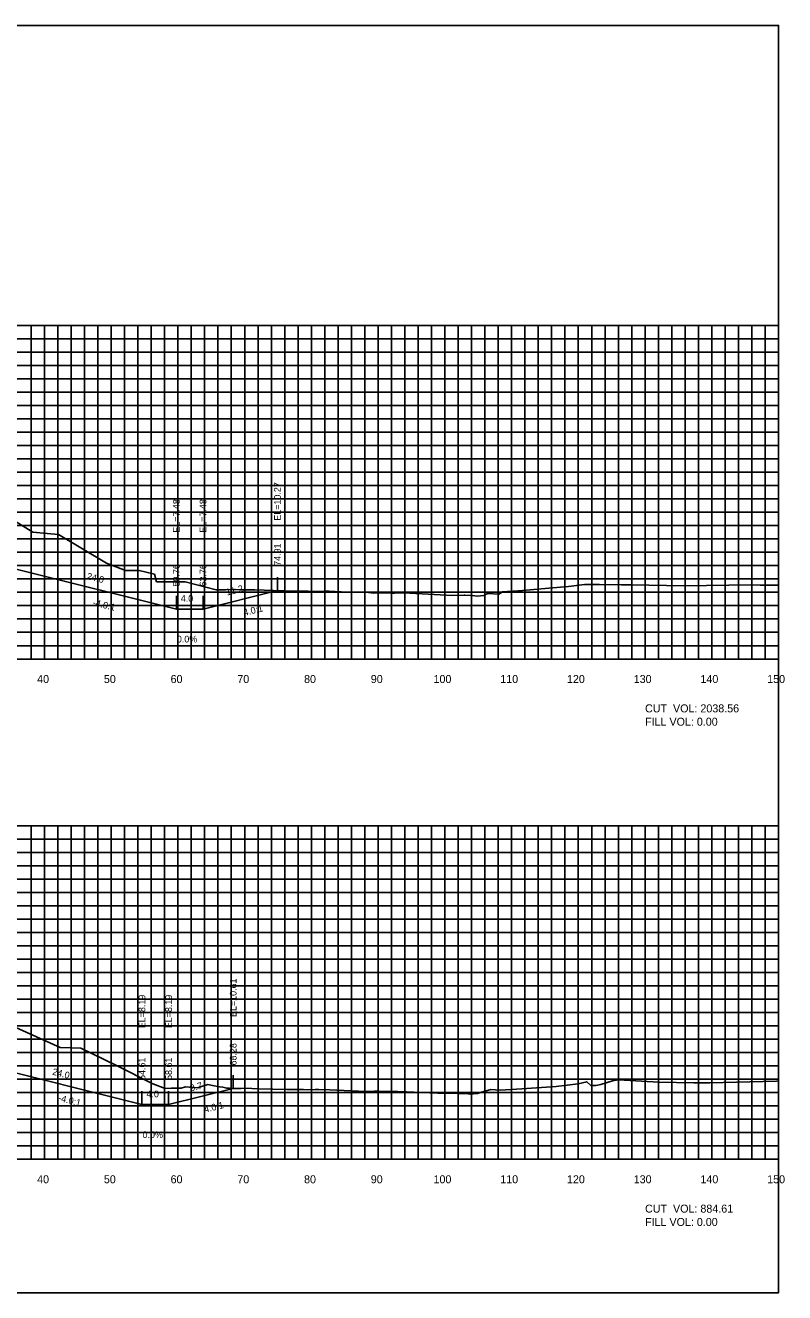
# Model space of a CAD drawing. Extents: x 1800976 to 1805104, y 250057 to 250580.
# Drawn here: x 1804368.1 to 1804481.9, y 250079.4 to 250269.4 of the extents above; entities that cross this region are included whole.
import ezdxf

# ---------------------------------------------------------------- set-up
doc = ezdxf.new("R2010")
doc.units = 0
for name, color, linetype in [('10', 7, 'Continuous'), ('3', 7, 'Continuous'), ('4', 7, 'Continuous'), ('60', 7, 'Continuous'), ('ANNO-TXT', 7, 'Continuous'), ('CL-CNST', 7, 'Continuous'), ('Level 62', 7, 'Continuous'), ('M-ROADS', 7, 'Continuous')]:
    doc.layers.add(name, color=color, linetype=linetype)

msp = doc.modelspace()

# ---------------------------------------------------------------- linework, layer by layer
for p, q in [((1804405.91, 250184.7), (1804405.91, 250186.7)), ((1804390.76, 250181.91), (1804390.76, 250183.91)), ((1804394.76, 250181.91), (1804394.76, 250183.91)), ((1804399.28, 250110.04), (1804399.28, 250112.04)), ((1804385.61, 250107.62), (1804385.61, 250109.62)), ((1804389.61, 250107.62), (1804389.61, 250109.62))]:
    msp.add_line(p, q)
msp.add_lwpolyline([(1804181, 250079.43), (1804481, 250079.43), (1804481, 250269.43), (1804181, 250269.43)], close=True)
at = {"layer": '60'}
for p, q in [((1804481, 250174.43), (1804481, 250224.43)), ((1804481.06, 250224.43), (1804481, 250224.43)), ((1804481.06, 250214.43), (1804481, 250214.43)), ((1804481.06, 250204.43), (1804481, 250204.43)), ((1804481.06, 250194.43), (1804481, 250194.43)), ((1804481.06, 250184.43), (1804481, 250184.43)), ((1804181, 250174.43), (1804481, 250174.43)), ((1804371, 250174.37), (1804371, 250174.43)), ((1804381, 250174.37), (1804381, 250174.43)), ((1804391, 250174.37), (1804391, 250174.43)), ((1804401, 250174.37), (1804401, 250174.43)), ((1804411, 250174.37), (1804411, 250174.43)), ((1804421, 250174.37), (1804421, 250174.43)), ((1804431, 250174.37), (1804431, 250174.43)), ((1804441, 250174.37), (1804441, 250174.43)), ((1804451, 250174.37), (1804451, 250174.43)), ((1804461, 250174.37), (1804461, 250174.43)), ((1804471, 250174.37), (1804471, 250174.43)), ((1804481, 250174.37), (1804481, 250174.43)), ((1804481.06, 250174.43), (1804481, 250174.43)), ((1804481, 250099.43), (1804481, 250149.43)), ((1804481.06, 250149.43), (1804481, 250149.43)), ((1804481.06, 250139.43), (1804481, 250139.43)), ((1804481.06, 250129.43), (1804481, 250129.43)), ((1804481.06, 250119.43), (1804481, 250119.43)), ((1804481.06, 250109.43), (1804481, 250109.43)), ((1804181, 250099.43), (1804481, 250099.43)), ((1804371, 250099.37), (1804371, 250099.43)), ((1804381, 250099.37), (1804381, 250099.43)), ((1804391, 250099.37), (1804391, 250099.43)), ((1804401, 250099.37), (1804401, 250099.43)), ((1804411, 250099.37), (1804411, 250099.43)), ((1804421, 250099.37), (1804421, 250099.43)), ((1804431, 250099.37), (1804431, 250099.43)), ((1804441, 250099.37), (1804441, 250099.43)), ((1804451, 250099.37), (1804451, 250099.43)), ((1804461, 250099.37), (1804461, 250099.43)), ((1804471, 250099.37), (1804471, 250099.43)), ((1804481, 250099.37), (1804481, 250099.43)), ((1804481.06, 250099.43), (1804481, 250099.43))]:
    msp.add_line(p, q, dxfattribs=at)
at = {"layer": 'CL-CNST'}
for points in [[(1804198.7, 250206.13), (1804259.65, 250185.81), (1804263.65, 250185.81), (1804284.65, 250189.31), (1804290.23, 250189.54), (1804294.23, 250189.7), (1804326.41, 250188.99), (1804326.81, 250188.98), (1804331, 250188.89), (1804356.21, 250188.33), (1804364.21, 250188.01), (1804366.76, 250187.91), (1804390.76, 250181.91), (1804394.76, 250181.91), (1804405.91, 250184.7)], [(1804287.75, 250115.49), (1804295, 250115.33), (1804331, 250114.54), (1804348.03, 250114.16), (1804356.03, 250113.84), (1804361.61, 250113.62), (1804385.61, 250107.62), (1804389.61, 250107.62), (1804399.28, 250110.04)]]:
    msp.add_lwpolyline(points, dxfattribs=at)
at = {"layer": 'Level 62'}
for p, q in [((1804181, 250224.43), (1804481, 250224.43)), ((1804369, 250174.43), (1804369, 250224.43)), ((1804371, 250174.43), (1804371, 250224.43)), ((1804373, 250174.43), (1804373, 250224.43)), ((1804375, 250174.43), (1804375, 250224.43)), ((1804377, 250174.43), (1804377, 250224.43)), ((1804379, 250174.43), (1804379, 250224.43)), ((1804381, 250174.43), (1804381, 250224.43)), ((1804383, 250174.43), (1804383, 250224.43)), ((1804385, 250174.43), (1804385, 250224.43)), ((1804387, 250174.43), (1804387, 250224.43)), ((1804389, 250174.43), (1804389, 250224.43)), ((1804391, 250174.43), (1804391, 250224.43)), ((1804393, 250174.43), (1804393, 250224.43)), ((1804395, 250174.43), (1804395, 250224.43)), ((1804397, 250174.43), (1804397, 250224.43)), ((1804399, 250174.43), (1804399, 250224.43)), ((1804401, 250174.43), (1804401, 250224.43)), ((1804403, 250174.43), (1804403, 250224.43)), ((1804405, 250174.43), (1804405, 250224.43)), ((1804407, 250174.43), (1804407, 250224.43)), ((1804409, 250174.43), (1804409, 250224.43)), ((1804411, 250174.43), (1804411, 250224.43)), ((1804413, 250174.43), (1804413, 250224.43)), ((1804415, 250174.43), (1804415, 250224.43)), ((1804417, 250174.43), (1804417, 250224.43)), ((1804419, 250174.43), (1804419, 250224.43)), ((1804421, 250174.43), (1804421, 250224.43)), ((1804423, 250174.43), (1804423, 250224.43)), ((1804425, 250174.43), (1804425, 250224.43)), ((1804427, 250174.43), (1804427, 250224.43)), ((1804429, 250174.43), (1804429, 250224.43)), ((1804431, 250174.43), (1804431, 250224.43)), ((1804433, 250174.43), (1804433, 250224.43)), ((1804435, 250174.43), (1804435, 250224.43)), ((1804437, 250174.43), (1804437, 250224.43)), ((1804439, 250174.43), (1804439, 250224.43)), ((1804441, 250174.43), (1804441, 250224.43)), ((1804443, 250174.43), (1804443, 250224.43)), ((1804445, 250174.43), (1804445, 250224.43)), ((1804447, 250174.43), (1804447, 250224.43)), ((1804449, 250174.43), (1804449, 250224.43)), ((1804451, 250174.43), (1804451, 250224.43)), ((1804453, 250174.43), (1804453, 250224.43)), ((1804455, 250174.43), (1804455, 250224.43)), ((1804457, 250174.43), (1804457, 250224.43)), ((1804459, 250174.43), (1804459, 250224.43)), ((1804461, 250174.43), (1804461, 250224.43)), ((1804463, 250174.43), (1804463, 250224.43)), ((1804465, 250174.43), (1804465, 250224.43)), ((1804467, 250174.43), (1804467, 250224.43)), ((1804469, 250174.43), (1804469, 250224.43)), ((1804471, 250174.43), (1804471, 250224.43)), ((1804473, 250174.43), (1804473, 250224.43)), ((1804475, 250174.43), (1804475, 250224.43)), ((1804477, 250174.43), (1804477, 250224.43)), ((1804479, 250174.43), (1804479, 250224.43)), ((1804481, 250174.43), (1804481, 250224.43)), ((1804181, 250222.43), (1804481, 250222.43)), ((1804181, 250220.43), (1804481, 250220.43)), ((1804181, 250218.43), (1804481, 250218.43)), ((1804181, 250216.43), (1804481, 250216.43)), ((1804181, 250214.43), (1804481, 250214.43)), ((1804181, 250212.43), (1804481, 250212.43)), ((1804181, 250210.43), (1804481, 250210.43)), ((1804181, 250208.43), (1804481, 250208.43)), ((1804181, 250206.43), (1804481, 250206.43)), ((1804181, 250204.43), (1804481, 250204.43)), ((1804181, 250202.43), (1804481, 250202.43)), ((1804181, 250200.43), (1804481, 250200.43)), ((1804181, 250198.43), (1804481, 250198.43)), ((1804181, 250196.43), (1804481, 250196.43)), ((1804181, 250194.43), (1804481, 250194.43)), ((1804181, 250192.43), (1804481, 250192.43)), ((1804181, 250190.43), (1804481, 250190.43)), ((1804181, 250188.43), (1804481, 250188.43)), ((1804181, 250186.43), (1804481, 250186.43)), ((1804181, 250184.43), (1804481, 250184.43)), ((1804181, 250182.43), (1804481, 250182.43)), ((1804181, 250180.43), (1804481, 250180.43)), ((1804181, 250178.43), (1804481, 250178.43)), ((1804181, 250176.43), (1804481, 250176.43)), ((1804181, 250174.43), (1804481, 250174.43)), ((1804181, 250149.43), (1804481, 250149.43)), ((1804369, 250099.43), (1804369, 250149.43)), ((1804371, 250099.43), (1804371, 250149.43)), ((1804373, 250099.43), (1804373, 250149.43)), ((1804375, 250099.43), (1804375, 250149.43)), ((1804377, 250099.43), (1804377, 250149.43)), ((1804379, 250099.43), (1804379, 250149.43)), ((1804381, 250099.43), (1804381, 250149.43)), ((1804383, 250099.43), (1804383, 250149.43)), ((1804385, 250099.43), (1804385, 250149.43)), ((1804387, 250099.43), (1804387, 250149.43)), ((1804389, 250099.43), (1804389, 250149.43)), ((1804391, 250099.43), (1804391, 250149.43)), ((1804393, 250099.43), (1804393, 250149.43)), ((1804395, 250099.43), (1804395, 250149.43)), ((1804397, 250099.43), (1804397, 250149.43)), ((1804399, 250099.43), (1804399, 250149.43)), ((1804401, 250099.43), (1804401, 250149.43)), ((1804403, 250099.43), (1804403, 250149.43)), ((1804405, 250099.43), (1804405, 250149.43)), ((1804407, 250099.43), (1804407, 250149.43)), ((1804409, 250099.43), (1804409, 250149.43)), ((1804411, 250099.43), (1804411, 250149.43)), ((1804413, 250099.43), (1804413, 250149.43)), ((1804415, 250099.43), (1804415, 250149.43)), ((1804417, 250099.43), (1804417, 250149.43)), ((1804419, 250099.43), (1804419, 250149.43)), ((1804421, 250099.43), (1804421, 250149.43)), ((1804423, 250099.43), (1804423, 250149.43)), ((1804425, 250099.43), (1804425, 250149.43)), ((1804427, 250099.43), (1804427, 250149.43)), ((1804429, 250099.43), (1804429, 250149.43)), ((1804431, 250099.43), (1804431, 250149.43)), ((1804433, 250099.43), (1804433, 250149.43)), ((1804435, 250099.43), (1804435, 250149.43)), ((1804437, 250099.43), (1804437, 250149.43)), ((1804439, 250099.43), (1804439, 250149.43)), ((1804441, 250099.43), (1804441, 250149.43)), ((1804443, 250099.43), (1804443, 250149.43)), ((1804445, 250099.43), (1804445, 250149.43)), ((1804447, 250099.43), (1804447, 250149.43)), ((1804449, 250099.43), (1804449, 250149.43)), ((1804451, 250099.43), (1804451, 250149.43)), ((1804453, 250099.43), (1804453, 250149.43)), ((1804455, 250099.43), (1804455, 250149.43)), ((1804457, 250099.43), (1804457, 250149.43)), ((1804459, 250099.43), (1804459, 250149.43)), ((1804461, 250099.43), (1804461, 250149.43)), ((1804463, 250099.43), (1804463, 250149.43)), ((1804465, 250099.43), (1804465, 250149.43)), ((1804467, 250099.43), (1804467, 250149.43)), ((1804469, 250099.43), (1804469, 250149.43)), ((1804471, 250099.43), (1804471, 250149.43)), ((1804473, 250099.43), (1804473, 250149.43)), ((1804475, 250099.43), (1804475, 250149.43)), ((1804477, 250099.43), (1804477, 250149.43)), ((1804479, 250099.43), (1804479, 250149.43)), ((1804481, 250099.43), (1804481, 250149.43)), ((1804181, 250147.43), (1804481, 250147.43)), ((1804181, 250145.43), (1804481, 250145.43)), ((1804181, 250143.43), (1804481, 250143.43)), ((1804181, 250141.43), (1804481, 250141.43)), ((1804181, 250139.43), (1804481, 250139.43)), ((1804181, 250137.43), (1804481, 250137.43)), ((1804181, 250135.43), (1804481, 250135.43)), ((1804181, 250133.43), (1804481, 250133.43)), ((1804181, 250131.43), (1804481, 250131.43)), ((1804181, 250129.43), (1804481, 250129.43)), ((1804181, 250127.43), (1804481, 250127.43)), ((1804181, 250125.43), (1804481, 250125.43)), ((1804181, 250123.43), (1804481, 250123.43)), ((1804181, 250121.43), (1804481, 250121.43)), ((1804181, 250119.43), (1804481, 250119.43)), ((1804181, 250117.43), (1804481, 250117.43)), ((1804181, 250115.43), (1804481, 250115.43)), ((1804181, 250113.43), (1804481, 250113.43)), ((1804181, 250111.43), (1804481, 250111.43)), ((1804181, 250109.43), (1804481, 250109.43)), ((1804181, 250107.43), (1804481, 250107.43)), ((1804181, 250105.43), (1804481, 250105.43)), ((1804181, 250103.43), (1804481, 250103.43)), ((1804181, 250101.43), (1804481, 250101.43)), ((1804181, 250099.43), (1804481, 250099.43))]:
    msp.add_line(p, q, dxfattribs=at)
at = {"layer": 'M-ROADS'}
for points in [[(1804359.51, 250199.42), (1804369.28, 250193.46), (1804371.41, 250193.26), (1804373.1, 250193.1), (1804380.3, 250188.78), (1804383.14, 250187.72), (1804383.93, 250187.72), (1804385.17, 250187.72), (1804387.48, 250187.15), (1804387.8, 250186.02), (1804389.44, 250186.02), (1804391.86, 250186.02), (1804391.98, 250186.02), (1804392.07, 250186), (1804396.74, 250184.8), (1804397.63, 250184.79), (1804397.7, 250184.79), (1804397.73, 250184.79), (1804398.13, 250184.81), (1804399.46, 250184.86), (1804399.61, 250184.85), (1804400.44, 250184.8), (1804400.6, 250184.79), (1804400.78, 250184.79), (1804401.05, 250184.79), (1804402.53, 250184.82), (1804405.34, 250184.72), (1804408.58, 250184.59), (1804410.16, 250184.61), (1804410.34, 250184.61), (1804410.37, 250184.61), (1804410.5, 250184.6), (1804411.4, 250184.57), (1804411.65, 250184.56), (1804412.92, 250184.58), (1804413.41, 250184.59), (1804413.68, 250184.58), (1804416.35, 250184.47), (1804418.24, 250184.47), (1804419.57, 250184.41), (1804420.36, 250184.32), (1804421.95, 250184.36), (1804422.13, 250184.36), (1804422.16, 250184.36), (1804422.25, 250184.35), (1804423.06, 250184.31), (1804423.43, 250184.29), (1804425.08, 250184.33), (1804425.19, 250184.33), (1804425.74, 250184.3), (1804432.12, 250183.97), (1804433.87, 250184), (1804433.93, 250184), (1804433.98, 250184), (1804434.86, 250183.97), (1804435.15, 250183.95), (1804435.86, 250183.83), (1804436.85, 250183.97), (1804437, 250184.06), (1804437.43, 250184.26), (1804439.07, 250184.17), (1804439.62, 250184.48), (1804441.91, 250184.64), (1804442.01, 250184.64), (1804442.08, 250184.64), (1804446.58, 250185.05), (1804449.54, 250185.31), (1804451.93, 250185.62), (1804454.19, 250185.62), (1804457.49, 250185.56), (1804458.87, 250185.53), (1804466.89, 250185.41), (1804476.83, 250185.53), (1804478.23, 250185.52), (1804479.89, 250185.52), (1804480.93, 250185.52), (1804481, 250185.52)], [(1804363.13, 250120.77), (1804373.33, 250116.2), (1804375.04, 250116.14), (1804376.47, 250116.09), (1804381.8, 250113.51), (1804387.23, 250110.72), (1804389.08, 250110.03), (1804390.01, 250110.1), (1804391.5, 250110.1), (1804392.15, 250110.29), (1804394, 250110.16), (1804394.1, 250110.18), (1804395.46, 250110.66), (1804396.16, 250110.49), (1804397.24, 250110.31), (1804397.72, 250110.24), (1804398.32, 250110.08), (1804398.71, 250110.07), (1804399.29, 250110.04), (1804400.44, 250110.06), (1804401.02, 250110.08), (1804403.12, 250110.01), (1804407.31, 250109.87), (1804408.3, 250109.89), (1804408.93, 250109.89), (1804409.57, 250109.89), (1804409.8, 250109.88), (1804410.4, 250109.86), (1804411.54, 250109.88), (1804412.12, 250109.89), (1804413.77, 250109.82), (1804419.11, 250109.6), (1804420.46, 250109.62), (1804420.84, 250109.62), (1804420.91, 250109.62), (1804421.85, 250109.58), (1804421.98, 250109.57), (1804422, 250109.57), (1804422.15, 250109.58), (1804423.29, 250109.6), (1804423.93, 250109.61), (1804425.26, 250109.55), (1804431.08, 250109.3), (1804432.33, 250109.32), (1804432.79, 250109.32), (1804433.14, 250109.31), (1804433.65, 250109.29), (1804434.16, 250109.28), (1804434.81, 250109.21), (1804435.77, 250109.27), (1804435.89, 250109.3), (1804436.33, 250109.43), (1804437.9, 250109.87), (1804439.28, 250109.81), (1804442.55, 250109.99), (1804447.66, 250110.32), (1804450.96, 250110.74), (1804452.26, 250111.04), (1804452.87, 250110.49), (1804453.62, 250110.49), (1804454.37, 250110.66), (1804456.13, 250111.21), (1804457.04, 250111.32), (1804463.04, 250111.01), (1804468.31, 250110.9), (1804470.71, 250110.87), (1804480.71, 250111.16), (1804481, 250111.17)]]:
    msp.add_lwpolyline(points, dxfattribs=at)

# ---------------------------------------------------------------- texts
for s, rotation, p in [('-4.0:1', 345.9638, (1804378.15, 250182.48)), ('4.0:1', 14.0362, (1804400.94, 250180.88)), ('-4.0:1', 345.9638, (1804373, 250108.19)), ('4.0:1', 14.0362, (1804395.05, 250106.4))]:
    msp.add_text(s, height=1, rotation=rotation).set_placement(p)
at = {"layer": '10'}
for s, p in [('40', (1804369.9, 250170.83)), ('50', (1804379.9, 250170.83)), ('60', (1804389.9, 250170.83)), ('70', (1804399.9, 250170.83)), ('80', (1804409.9, 250170.83)), ('90', (1804419.9, 250170.83)), ('100', (1804429.3, 250170.83)), ('110', (1804439.3, 250170.83)), ('120', (1804449.3, 250170.83)), ('130', (1804459.3, 250170.83)), ('140', (1804469.3, 250170.83)), ('150', (1804479.3, 250170.83)), ('40', (1804369.9, 250095.83)), ('50', (1804379.9, 250095.83)), ('60', (1804389.9, 250095.83)), ('70', (1804399.9, 250095.83)), ('80', (1804409.9, 250095.83)), ('90', (1804419.9, 250095.83)), ('100', (1804429.3, 250095.83)), ('110', (1804439.3, 250095.83)), ('120', (1804449.3, 250095.83)), ('130', (1804459.3, 250095.83)), ('140', (1804469.3, 250095.83)), ('150', (1804479.3, 250095.83))]:
    msp.add_text(s, height=1.2, dxfattribs=at).set_placement(p)
at = {"layer": '3'}
for s, p in [('EL=10.27', (1804406.41, 250195.17)), ('EL=7.48', (1804391.26, 250193.37)), ('EL=7.48', (1804395.26, 250193.37)), ('74.91', (1804406.41, 250188.4)), ('59.76', (1804391.26, 250185.31)), ('63.76', (1804395.26, 250185.31)), ('EL=10.61', (1804399.78, 250120.76)), ('EL=8.19', (1804386.11, 250119.08)), ('EL=8.19', (1804390.11, 250119.08)), ('68.28', (1804399.78, 250113.49)), ('54.61', (1804386.11, 250111.32)), ('58.61', (1804390.11, 250111.32))]:
    msp.add_text(s, height=1, rotation=90, dxfattribs=at).set_placement(p)
at = {"layer": '4'}
for s, rotation, p in [('24.0', 345.9638, (1804377.26, 250186.42)), ('11.2', 14.0362, (1804398.34, 250183.94)), ('24.0', 345.9638, (1804372.11, 250112.13)), ('9.7', 14.0362, (1804392.94, 250109.59))]:
    msp.add_text(s, height=1, rotation=rotation, dxfattribs=at).set_placement(p)
for s, p in [('4.0', (1804391.43, 250183.01)), ('0.0%', (1804390.84, 250176.91)), ('4.0', (1804386.29, 250108.72)), ('0.0%', (1804385.7, 250102.62))]:
    msp.add_text(s, height=1, dxfattribs=at).set_placement(p)
at = {"layer": 'ANNO-TXT'}
for s, p in [('CUT  VOL: 2038.56', (1804461, 250166.43)), ('FILL VOL: 0.00', (1804461, 250164.43)), ('CUT  VOL: 884.61', (1804461, 250091.43)), ('FILL VOL: 0.00', (1804461, 250089.43))]:
    msp.add_text(s, height=1.2, dxfattribs=at).set_placement(p)

doc.saveas('drawing.dxf')
